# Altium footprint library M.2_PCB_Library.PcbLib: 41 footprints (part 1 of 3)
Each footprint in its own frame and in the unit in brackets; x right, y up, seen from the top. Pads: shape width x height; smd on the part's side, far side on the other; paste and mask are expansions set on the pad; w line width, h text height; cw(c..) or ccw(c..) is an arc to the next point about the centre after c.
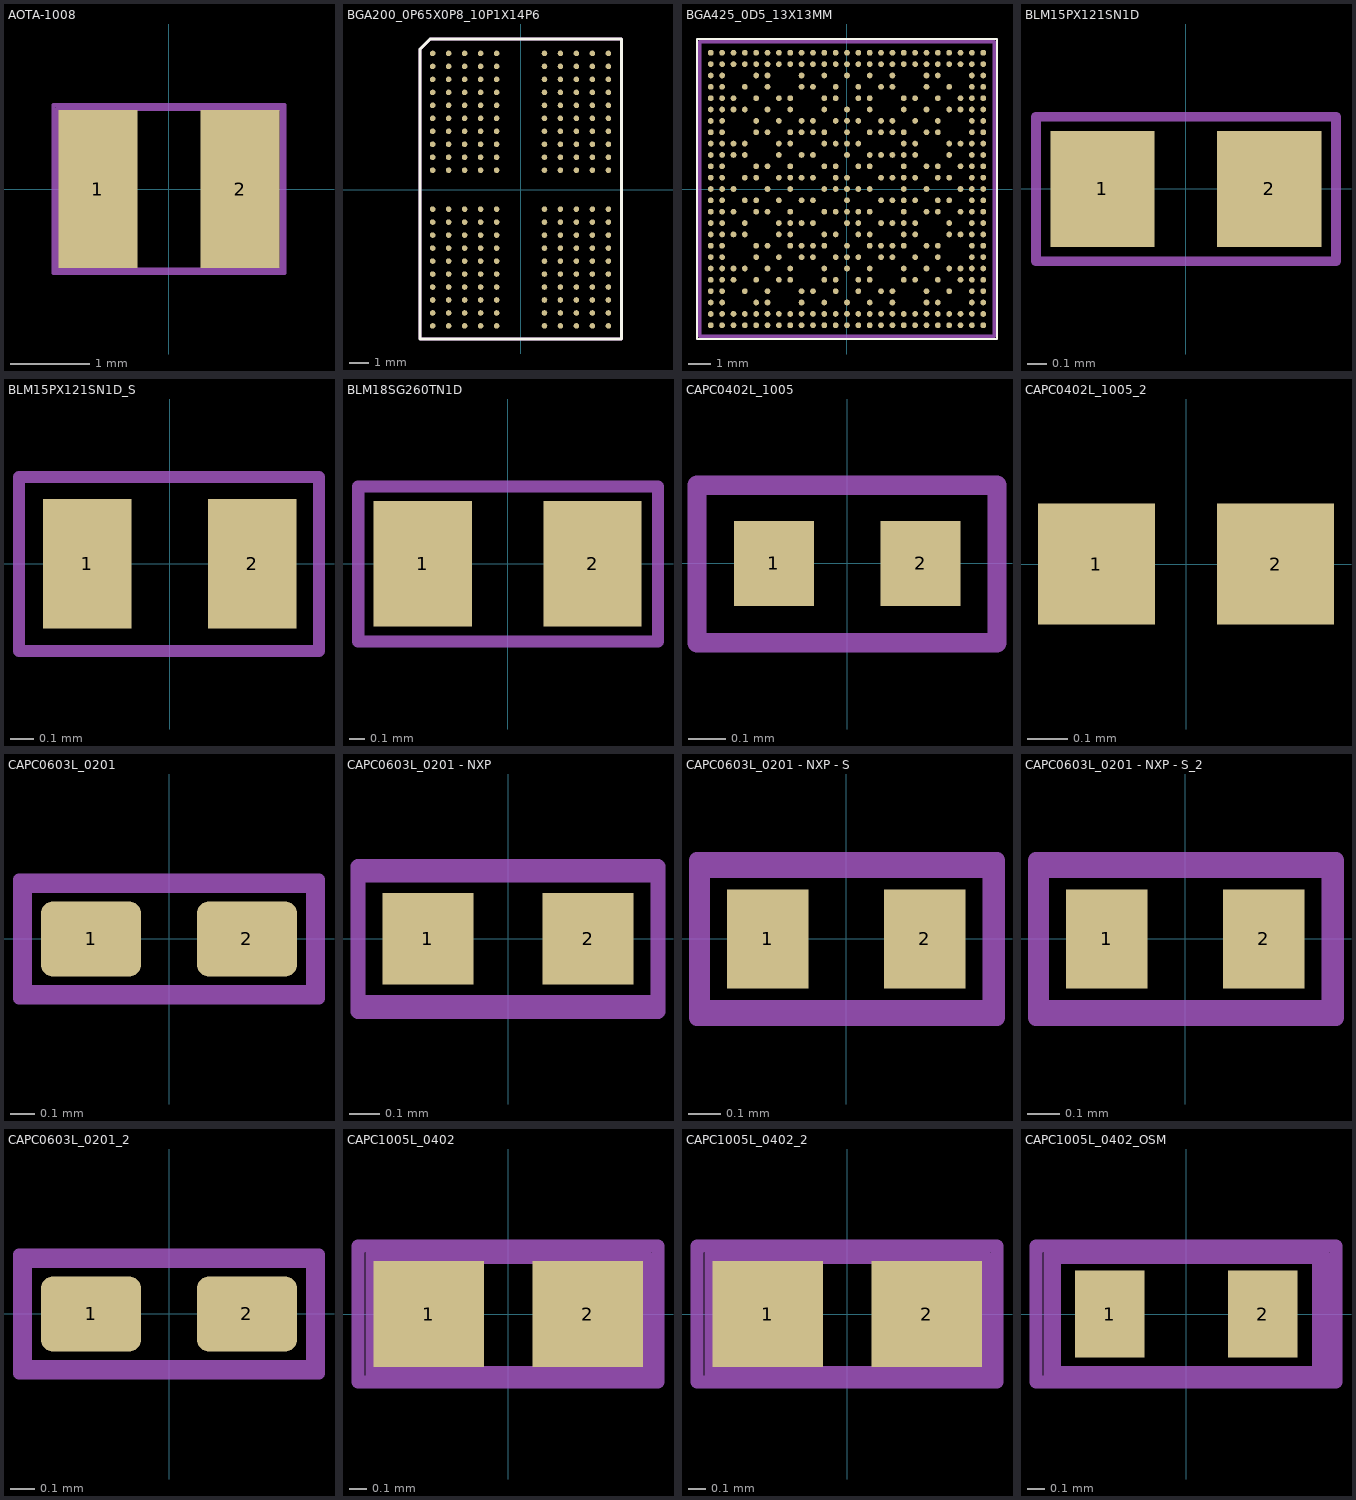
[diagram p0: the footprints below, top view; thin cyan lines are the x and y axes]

## AOTA-1008 [mm]
pads (2):
  rect 1x2 smd paste-0.043 mask+0.038: 1(-0.9,0) 2(0.9,0)
Mechanical 1:
Mechanical 9:
  lines w0.051: -1.46,-1.064 -1.46,1.065 1.465,1.065 1.465,-1.064 -1.46,-1.064
Top Assembly:
  lines w0.051: -1.419,-1.022 -1.419,1.015 1.428,1.015 1.428,-1.022 -1.419,-1.022
  text "'.Designator'" at -0.413,-0.106 h0.2
3D body "AOTA-B252010SR33MT.stp": height 1, standoff 0, extent -1.25,-1 1.25,1

## BGA200_0P65X0P8_10P1X14P6 [mil] "BGA200_0P65X0P8_10P1X14P6"
pads (200):
  round 11 smd mask+2.76: A1(-173.23,268.7) A2(-141.73,268.7) A3(-110.24,268.7) A4(-78.74,268.7) A5(-47.24,268.7) A8(47.24,268.7) A9(78.74,268.7) A10(110.24,268.7) A11(141.73,268.7) A12(173.23,268.7) AA1(-173.23,-243.11) AA2(-141.73,-243.11) AA3(-110.24,-243.11) AA4(-78.74,-243.11) AA5(-47.24,-243.11) AA8(47.24,-243.11) AA9(78.74,-243.11) AA10(110.24,-243.11) AA11(141.73,-243.11) AA12(173.23,-243.11) AB1(-173.23,-268.7) AB2(-141.73,-268.7) AB3(-110.24,-268.7) AB4(-78.74,-268.7) AB5(-47.24,-268.7) AB8(47.24,-268.7) AB9(78.74,-268.7) AB10(110.24,-268.7) AB11(141.73,-268.7) AB12(173.23,-268.7) B1(-173.23,243.11) B2(-141.73,243.11) B3(-110.24,243.11) B4(-78.74,243.11) B5(-47.24,243.11) B8(47.24,243.11) B9(78.74,243.11) B10(110.24,243.11) B11(141.73,243.11) B12(173.23,243.11) C1(-173.23,217.52) C2(-141.73,217.52) C3(-110.24,217.52) C4(-78.74,217.52) C5(-47.24,217.52) C8(47.24,217.52) C9(78.74,217.52) C10(110.24,217.52) C11(141.73,217.52) C12(173.23,217.52) D1(-173.23,191.93) D2(-141.73,191.93) D3(-110.24,191.93) D4(-78.74,191.93) D5(-47.24,191.93) D8(47.24,191.93) D9(78.74,191.93) D10(110.24,191.93) D11(141.73,191.93) D12(173.23,191.93) E1(-173.23,166.34) E2(-141.73,166.34) E3(-110.24,166.34) E4(-78.74,166.34) E5(-47.24,166.34) E8(47.24,166.34) E9(78.74,166.34) E10(110.24,166.34) E11(141.73,166.34) E12(173.23,166.34) F1(-173.23,140.75) F2(-141.73,140.75) F3(-110.24,140.75) F4(-78.74,140.75) F5(-47.24,140.75) F8(47.24,140.75) F9(78.74,140.75) F10(110.24,140.75) F11(141.73,140.75) F12(173.23,140.75) G1(-173.23,115.16) G2(-141.73,115.16) G3(-110.24,115.16) G4(-78.74,115.16) G5(-47.24,115.16) G8(47.24,115.16) G9(78.74,115.16) G10(110.24,115.16) G11(141.73,115.16) G12(173.23,115.16) H1(-173.23,89.57) H2(-141.73,89.57) H3(-110.24,89.57) H4(-78.74,89.57) H5(-47.24,89.57) H8(47.24,89.57) H9(78.74,89.57) H10(110.24,89.57) H11(141.73,89.57) H12(173.23,89.57) J1(-173.23,63.98) J2(-141.73,63.98) J3(-110.24,63.98) J4(-78.74,63.98) J5(-47.24,63.98) J8(47.24,63.98) J9(78.74,63.98) J10(110.24,63.98) J11(141.73,63.98) J12(173.23,63.98) K1(-173.23,38.39) K2(-141.73,38.39) K3(-110.24,38.39) K4(-78.74,38.39) K5(-47.24,38.39) K8(47.24,38.39) K9(78.74,38.39) K10(110.24,38.39) K11(141.73,38.39) K12(173.23,38.39) N1(-173.23,-38.39) N2(-141.73,-38.39) N3(-110.24,-38.39) N4(-78.74,-38.39) N5(-47.24,-38.39) N8(47.24,-38.39) N9(78.74,-38.39) N10(110.24,-38.39) N11(141.73,-38.39) N12(173.23,-38.39) P1(-173.23,-63.98) P2(-141.73,-63.98) P3(-110.24,-63.98) P4(-78.74,-63.98) P5(-47.24,-63.98) P8(47.24,-63.98) P9(78.74,-63.98) P10(110.24,-63.98) P11(141.73,-63.98) P12(173.23,-63.98) R1(-173.23,-89.57) R2(-141.73,-89.57) R3(-110.24,-89.57) R4(-78.74,-89.57) R5(-47.24,-89.57) R8(47.24,-89.57) R9(78.74,-89.57) R10(110.24,-89.57) R11(141.73,-89.57) R12(173.23,-89.57) T1(-173.23,-115.16) T2(-141.73,-115.16) T3(-110.24,-115.16) T4(-78.74,-115.16) T5(-47.24,-115.16) T8(47.24,-115.16) T9(78.74,-115.16) T10(110.24,-115.16) T11(141.73,-115.16) T12(173.23,-115.16) U1(-173.23,-140.75) U2(-141.73,-140.75) U3(-110.24,-140.75) U4(-78.74,-140.75) U5(-47.24,-140.75) U8(47.24,-140.75) U9(78.74,-140.75) U10(110.24,-140.75) U11(141.73,-140.75) U12(173.23,-140.75) V1(-173.23,-166.34) V2(-141.73,-166.34) V3(-110.24,-166.34) V4(-78.74,-166.34) V5(-47.24,-166.34) V8(47.24,-166.34) V9(78.74,-166.34) V10(110.24,-166.34) V11(141.73,-166.34) V12(173.23,-166.34) W1(-173.23,-191.93) W2(-141.73,-191.93) W3(-110.24,-191.93) W4(-78.74,-191.93) W5(-47.24,-191.93) W8(47.24,-191.93) W9(78.74,-191.93) W10(110.24,-191.93) W11(141.73,-191.93) W12(173.23,-191.93) Y1(-173.23,-217.52) Y2(-141.73,-217.52) Y3(-110.24,-217.52) Y4(-78.74,-217.52) Y5(-47.24,-217.52) Y8(47.24,-217.52) Y9(78.74,-217.52) Y10(110.24,-217.52) Y11(141.73,-217.52) Y12(173.23,-217.52)
Top Overlay:
  lines w6: -198.21,-294.41 198.86,-294.41 198.86,297.15 -178.07,297.15 -198.21,277.01 -198.21,-294.41
Mechanical 7:
  text "'.Designator'" at -66.73,-11.32 h50
  text "AB" at -238.87,-258 h25
  text "A" at -238.87,277 h25
  text "1" at -194.7,322 h25
  text "12" at 215.16,299.31 h25
Top Assembly:
  lines w6: -198.31,-294.43 -198.31,276.91 -178.07,297.15 198.82,297.15 198.82,-294.43 -198.31,-294.43
Mechanical 18:
  text "K8" at 47.24,38.71 h0.4
  text "N8" at 47.24,-38.07 h0.4
  text "K5" at -47.24,38.71 h0.4
  text "N5" at -47.24,-38.07 h0.4
  text "AB12" at 173.23,-268.06 h0.4
  text "A11" at 141.73,269.18 h0.4
  text "A2" at -141.73,269.02 h0.4
  text "A1" at -173.23,269.02 h0.4
  text "AB11" at 141.73,-268.06 h0.4
  text "AB2" at -141.73,-268.22 h0.4
  text "AB1" at -173.23,-268.22 h0.4
  text "AA12" at 173.23,-242.47 h0.4
  text "AA1" at -173.23,-242.63 h0.4
  text "B12" at 173.23,243.59 h0.4
  text "B1" at -173.23,243.43 h0.4
  text "A12" at 173.23,269.18 h0.4
  text "G11" at 141.73,115.64 h0.4
  text "T1" at -173.23,-114.84 h0.4
  text "V1" at -173.23,-166.02 h0.4
  text "D2" at -141.73,192.25 h0.4
  text "T3" at -110.24,-114.84 h0.4
  text "V12" at 173.23,-165.86 h0.4
  text "T12" at 173.23,-114.68 h0.4
  text "Y12" at 173.23,-217.04 h0.4
  text "P12" at 173.23,-63.5 h0.4
  text "N11" at 141.73,-37.91 h0.4
  text "J12" at 173.23,64.46 h0.4
  text "K11" at 141.73,38.87 h0.4
  text "G12" at 173.23,115.64 h0.4
  text "E12" at 173.23,166.82 h0.4
  text "AB8" at 47.24,-268.22 h0.4
  text "AB10" at 110.24,-268.06 h0.4
  text "Y8" at 47.24,-217.2 h0.4
  text "W9" at 78.74,-191.61 h0.4
  text "V8" at 47.24,-166.02 h0.4
  text "W11" at 141.73,-191.45 h0.4
  text "T10" at 110.24,-114.68 h0.4
  text "N9" at 78.74,-38.07 h0.4
  text "P10" at 110.24,-63.5 h0.4
  text "K9" at 78.74,38.71 h0.4
  text "J10" at 110.24,64.46 h0.4
  text "G8" at 47.24,115.48 h0.4
  text "C8" at 47.24,217.84 h0.4
  text "E8" at 47.24,166.66 h0.4
  text "G10" at 110.24,115.64 h0.4
  text "D9" at 78.74,192.25 h0.4
  text "A10" at 110.24,269.18 h0.4
  text "AB5" at -47.24,-268.22 h0.4
  text "W4" at -78.74,-191.61 h0.4
  text "Y5" at -47.24,-217.2 h0.4
  text "N4" at -78.74,-38.07 h0.4
  text "P3" at -110.24,-63.66 h0.4
  text "K4" at -78.74,38.71 h0.4
  text "J3" at -110.24,64.3 h0.4
  text "G3" at -110.24,115.48 h0.4
  text "G5" at -47.24,115.48 h0.4
  text "Y1" at -173.23,-217.2 h0.4
  text "D4" at -78.74,192.25 h0.4
  text "W2" at -141.73,-191.61 h0.4
  text "AB3" at -110.24,-268.22 h0.4
  text "N2" at -141.73,-38.07 h0.4
  text "P1" at -173.23,-63.66 h0.4
  text "G1" at -173.23,115.48 h0.4
  text "J1" at -173.23,64.3 h0.4
  text "K2" at -141.73,38.71 h0.4
  text "C5" at -47.24,217.84 h0.4
  text "C1" at -173.23,217.84 h0.4
  text "D11" at 141.73,192.41 h0.4
  text "C12" at 173.23,218 h0.4
  text "E1" at -173.23,166.66 h0.4
  text "A3" at -110.24,269.02 h0.4
  text "E5" at -47.24,166.66 h0.4
  text "V5" at -47.24,-166.02 h0.4
  text "T8" at 47.24,-114.84 h0.4
  text "T5" at -47.24,-114.84 h0.4
  text "J11" at 141.73,64.46 h0.4
  text "R2" at -141.73,-89.25 h0.4
  text "P9" at 78.74,-63.66 h0.4
  text "R4" at -78.74,-89.25 h0.4
  text "C4" at -78.74,217.84 h0.4
  text "F11" at 141.73,141.23 h0.4
  text "B4" at -78.74,243.43 h0.4
  text "C3" at -110.24,217.84 h0.4
  text "P2" at -141.73,-63.66 h0.4
  text "F2" at -141.73,141.07 h0.4
  text "T11" at 141.73,-114.68 h0.4
  text "Y9" at 78.74,-217.2 h0.4
  text "P11" at 141.73,-63.5 h0.4
  text "AA2" at -141.73,-242.63 h0.4
  text "T2" at -141.73,-114.84 h0.4
  text "AA11" at 141.73,-242.47 h0.4
  text "U9" at 78.74,-140.43 h0.4
  text "D3" at -110.24,192.25 h0.4
  text "F4" at -78.74,141.07 h0.4
  text "Y2" at -141.73,-217.2 h0.4
  text "Y11" at 141.73,-217.04 h0.4
  text "A5" at -47.24,269.02 h0.4
  text "H2" at -141.73,89.89 h0.4
  text "AA9" at 78.74,-242.63 h0.4
  text "E9" at 78.74,166.66 h0.4
  text "J4" at -78.74,64.3 h0.4
  text "H9" at 78.74,89.89 h0.4
  text "E11" at 141.73,166.82 h0.4
  text "V10" at 110.24,-165.86 h0.4
  text "U4" at -78.74,-140.43 h0.4
  text "C2" at -141.73,217.84 h0.4
  text "V11" at 141.73,-165.86 h0.4
  text "E3" at -110.24,166.66 h0.4
  text "AA4" at -78.74,-242.63 h0.4
  text "J9" at 78.74,64.3 h0.4
  text "J5" at -47.24,64.3 h0.4
  text "V4" at -78.74,-166.02 h0.4
  text "E4" at -78.74,166.66 h0.4
  text "B2" at -141.73,243.43 h0.4
  text "C9" at 78.74,217.84 h0.4
  text "U2" at -141.73,-140.43 h0.4
  text "H3" at -110.24,89.89 h0.4
  text "R3" at -110.24,-89.25 h0.4
  text "V2" at -141.73,-166.02 h0.4
  text "Y4" at -78.74,-217.2 h0.4
  text "E2" at -141.73,166.66 h0.4
  text "V3" at -110.24,-166.02 h0.4
  text "Y10" at 110.24,-217.04 h0.4
  text "J2" at -141.73,64.3 h0.4
  text "P4" at -78.74,-63.66 h0.4
  text "B3" at -110.24,243.43 h0.4
  text "U3" at -110.24,-140.43 h0.4
  text "W5" at -47.24,-191.61 h0.4
  text "U5" at -47.24,-140.43 h0.4
  text "H5" at -47.24,89.89 h0.4
  text "AA10" at 110.24,-242.47 h0.4
  text "W12" at 173.23,-191.45 h0.4
  text "U10" at 110.24,-140.27 h0.4
  text "R12" at 173.23,-89.09 h0.4
  text "N12" at 173.23,-37.91 h0.4
  text "N10" at 110.24,-37.91 h0.4
  text "K12" at 173.23,38.87 h0.4
  text "K10" at 110.24,38.87 h0.4
  text "H12" at 173.23,90.05 h0.4
  text "D12" at 173.23,192.41 h0.4
  text "F10" at 110.24,141.23 h0.4
  text "B10" at 110.24,243.59 h0.4
  text "AB9" at 78.74,-268.22 h0.4
  text "AA8" at 47.24,-242.63 h0.4
  text "W8" at 47.24,-191.61 h0.4
  text "U8" at 47.24,-140.43 h0.4
  text "R8" at 47.24,-89.25 h0.4
  text "H8" at 47.24,89.89 h0.4
  text "F8" at 47.24,141.07 h0.4
  text "F5" at -47.24,141.07 h0.4
  text "D8" at 47.24,192.25 h0.4
  text "A9" at 78.74,269.02 h0.4
  text "B8" at 47.24,243.43 h0.4
  text "AB4" at -78.74,-268.22 h0.4
  text "AA5" at -47.24,-242.63 h0.4
  text "D5" at -47.24,192.25 h0.4
  text "A4" at -78.74,269.02 h0.4
  text "B5" at -47.24,243.43 h0.4
  text "W1" at -173.23,-191.61 h0.4
  text "N3" at -110.24,-38.07 h0.4
  text "R1" at -173.23,-89.25 h0.4
  text "N1" at -173.23,-38.07 h0.4
  text "K3" at -110.24,38.71 h0.4
  text "K1" at -173.23,38.71 h0.4
  text "F3" at -110.24,141.07 h0.4
  text "H1" at -173.23,89.89 h0.4
  text "D1" at -173.23,192.25 h0.4
  text "AA3" at -110.24,-242.63 h0.4
  text "R5" at -47.24,-89.25 h0.4
  text "W10" at 110.24,-191.45 h0.4
  text "B11" at 141.73,243.59 h0.4
  text "A8" at 47.24,269.02 h0.4
  text "U12" at 173.23,-140.27 h0.4
  text "T4" at -78.74,-114.84 h0.4
  text "U1" at -173.23,-140.43 h0.4
  text "F1" at -173.23,141.07 h0.4
  text "G4" at -78.74,115.48 h0.4
  text "F12" at 173.23,141.23 h0.4
  text "G9" at 78.74,115.48 h0.4
  text "T9" at 78.74,-114.84 h0.4
  text "C10" at 110.24,218 h0.4
  text "F9" at 78.74,141.07 h0.4
  text "B9" at 78.74,243.43 h0.4
  text "H11" at 141.73,90.05 h0.4
  text "E10" at 110.24,166.82 h0.4
  text "H10" at 110.24,90.05 h0.4
  text "R9" at 78.74,-89.25 h0.4
  text "D10" at 110.24,192.41 h0.4
  text "V9" at 78.74,-166.02 h0.4
  text "P5" at -47.24,-63.66 h0.4
  text "C11" at 141.73,218 h0.4
  text "Y3" at -110.24,-217.2 h0.4
  text "H4" at -78.74,89.89 h0.4
  text "U11" at 141.73,-140.27 h0.4
  text "G2" at -141.73,115.48 h0.4
  text "P8" at 47.24,-63.66 h0.4
  text "W3" at -110.24,-191.61 h0.4
  text "R11" at 141.73,-89.09 h0.4
  text "R10" at 110.24,-89.09 h0.4
  text "J8" at 47.24,64.3 h0.4
Mechanical 19:
  text "AB" at -231,-257 h25
  text "A" at -236.22,259.84 h25
  text "12" at 173.23,307.09 h25
  text "1" at -173.23,307.09 h25
3D body: height 35.43, standoff 0, extent -198.82,-295.28 198.82,295.28

## BGA425_0D5_13X13MM [mil] "BGA425_0D5_13X13MM"
pads (425):
  round 10 smd: A1(-236.22,236.22) A2(-216.54,236.22) A3(-196.85,236.22) A4(-177.16,236.22) A5(-157.48,236.22) A6(-137.8,236.22) A7(-118.11,236.22) A8(-98.42,236.22) A9(-78.74,236.22) A10(-59.06,236.22) A11(-39.37,236.22) A12(-19.68,236.22) A13(0,236.22) A14(19.68,236.22) A15(39.37,236.22) A16(59.06,236.22) A17(78.74,236.22) A18(98.42,236.22) A19(118.11,236.22) A20(137.8,236.22) A21(157.48,236.22) A22(177.16,236.22) A23(196.85,236.22) A24(216.54,236.22) A25(236.22,236.22) AA1(-236.22,-157.48) AA2(-216.54,-157.48) AA3(-196.85,-157.48) AA5(-157.48,-157.48) AA7(-118.11,-157.48) AA8(-98.42,-157.48) AA11(-39.37,-157.48) AA12(-19.68,-157.48) AA14(19.68,-157.48) AA15(39.37,-157.48) AA18(98.42,-157.48) AA19(118.11,-157.48) AA21(157.48,-157.48) AA23(196.85,-157.48) AA24(216.54,-157.48) AA25(236.22,-157.48) AB1(-236.22,-177.16) AB2(-216.54,-177.16) AB4(-177.16,-177.16) AB6(-137.8,-177.16) AB9(-78.74,-177.16) AB10(-59.06,-177.16) AB12(-19.68,-177.16) AB14(19.68,-177.16) AB16(59.06,-177.16) AB17(78.74,-177.16) AB20(137.8,-177.16) AB22(177.16,-177.16) AB24(216.54,-177.16) AB25(236.22,-177.16) AC1(-236.22,-196.85) AC2(-216.54,-196.85) AC5(-157.48,-196.85) AC6(-137.8,-196.85) AC9(-78.74,-196.85) AC11(-39.37,-196.85) AC13(0,-196.85) AC15(39.37,-196.85) AC17(78.74,-196.85) AC20(137.8,-196.85) AC21(157.48,-196.85) AC24(216.54,-196.85) AC25(236.22,-196.85) AD1(-236.22,-216.54) AD2(-216.54,-216.54) AD3(-196.85,-216.54) AD4(-177.16,-216.54) AD5(-157.48,-216.54) AD6(-137.8,-216.54) AD7(-118.11,-216.54) AD8(-98.42,-216.54) AD9(-78.74,-216.54) AD10(-59.06,-216.54) AD11(-39.37,-216.54) AD12(-19.68,-216.54) AD13(0,-216.54) AD14(19.68,-216.54) AD15(39.37,-216.54) AD16(59.06,-216.54) AD17(78.74,-216.54) AD18(98.42,-216.54) AD19(118.11,-216.54) AD20(137.8,-216.54) AD21(157.48,-216.54) AD22(177.16,-216.54) AD23(196.85,-216.54) AD24(216.54,-216.54) AD25(236.22,-216.54) AE1(-236.22,-236.22) AE2(-216.54,-236.22) AE3(-196.85,-236.22) AE4(-177.16,-236.22) AE5(-157.48,-236.22) AE6(-137.8,-236.22) AE7(-118.11,-236.22) AE8(-98.42,-236.22) AE9(-78.74,-236.22) AE10(-59.06,-236.22) AE11(-39.37,-236.22) AE12(-19.68,-236.22) AE13(0,-236.22) AE14(19.68,-236.22) AE15(39.37,-236.22) AE16(59.06,-236.22) AE17(78.74,-236.22) AE18(98.42,-236.22) AE19(118.11,-236.22) AE20(137.8,-236.22) AE21(157.48,-236.22) AE22(177.16,-236.22) AE23(196.85,-236.22) AE24(216.54,-236.22) AE25(236.22,-236.22) B1(-236.22,216.54) B2(-216.54,216.54) B3(-196.85,216.54) B4(-177.16,216.54) B5(-157.48,216.54) B6(-137.8,216.54) B7(-118.11,216.54) B8(-98.42,216.54) B9(-78.74,216.54) B10(-59.06,216.54) B11(-39.37,216.54) B12(-19.68,216.54) B13(0,216.54) B14(19.68,216.54) B15(39.37,216.54) B16(59.06,216.54) B17(78.74,216.54) B18(98.42,216.54) B19(118.11,216.54) B20(137.8,216.54) B21(157.48,216.54) B22(177.16,216.54) B23(196.85,216.54) B24(216.54,216.54) B25(236.22,216.54) C1(-236.22,196.85) C2(-216.54,196.85) C5(-157.48,196.85) C6(-137.8,196.85) C9(-78.74,196.85) C11(-39.37,196.85) C13(0,196.85) C15(39.37,196.85) C17(78.74,196.85) C20(137.8,196.85) C21(157.48,196.85) C24(216.54,196.85) C25(236.22,196.85) D1(-236.22,177.16) D2(-216.54,177.16) D4(-177.16,177.16) D6(-137.8,177.16) D9(-78.74,177.16) D10(-59.06,177.16) D12(-19.68,177.16) D14(19.68,177.16) D16(59.06,177.16) D17(78.74,177.16) D20(137.8,177.16) D22(177.16,177.16) D24(216.54,177.16) D25(236.22,177.16) E1(-236.22,157.48) E2(-216.54,157.48) E3(-196.85,157.48) E5(-157.48,157.48) E7(-118.11,157.48) E8(-98.42,157.48) E11(-39.37,157.48) E12(-19.68,157.48) E14(19.68,157.48) E15(39.37,157.48) E18(98.42,157.48) E19(118.11,157.48) E21(157.48,157.48) E23(196.85,157.48) E24(216.54,157.48) E25(236.22,157.48) F1(-236.22,137.8) F2(-216.54,137.8) F3(-196.85,137.8) F4(-177.16,137.8) F6(-137.8,137.8) F8(-98.42,137.8) F11(-39.37,137.8) F13(0,137.8) F15(39.37,137.8) F18(98.42,137.8) F20(137.8,137.8) F22(177.16,137.8) F23(196.85,137.8) F24(216.54,137.8) F25(236.22,137.8) G1(-236.22,118.11) G2(-216.54,118.11) G5(-157.48,118.11) G7(-118.11,118.11) G9(-78.74,118.11) G10(-59.06,118.11) G12(-19.68,118.11) G13(0,118.11) G14(19.68,118.11) G16(59.06,118.11) G17(78.74,118.11) G19(118.11,118.11) G21(157.48,118.11) G24(216.54,118.11) G25(236.22,118.11) H1(-236.22,98.42) H2(-216.54,98.42) H5(-157.48,98.42) H6(-137.8,98.42) H8(-98.42,98.42) H9(-78.74,98.42) H10(-59.06,98.42) H11(-39.37,98.42) H13(0,98.42) H15(39.37,98.42) H16(59.06,98.42) H17(78.74,98.42) H18(98.42,98.42) H20(137.8,98.42) H21(157.48,98.42) H24(216.54,98.42) H25(236.22,98.42) J1(-236.22,78.74) J2(-216.54,78.74) J3(-196.85,78.74) J4(-177.16,78.74) J7(-118.11,78.74) J8(-98.42,78.74) J11(-39.37,78.74) J12(-19.68,78.74) J13(0,78.74) J14(19.68,78.74) J18(98.42,78.74) J19(118.11,78.74) J22(177.16,78.74) J23(196.85,78.74) J24(216.54,78.74) J25(236.22,78.74) K1(-236.22,59.06) K2(-216.54,59.06) K3(-196.85,59.06) K4(-177.16,59.06) K7(-118.11,59.06) K9(-78.74,59.06) K10(-59.06,59.06) K13(0,59.06) K15(39.37,59.06) K16(59.06,59.06) K17(78.74,59.06) K18(98.42,59.06) K19(118.11,59.06) K22(177.16,59.06) K24(216.54,59.06) K25(236.22,59.06) L1(-236.22,39.37) L2(-216.54,39.37) L5(-157.48,39.37) L6(-137.8,39.37) L8(-98.42,39.37) L11(-39.37,39.37) L12(-19.68,39.37) L14(19.68,39.37) L15(39.37,39.37) L18(98.42,39.37) L20(137.8,39.37) L21(157.48,39.37) L23(196.85,39.37) L24(216.54,39.37) L25(236.22,39.37) M1(-236.22,19.68) M2(-216.54,19.68) M4(-177.16,19.68) M5(-157.48,19.68) M7(-118.11,19.68) M8(-98.42,19.68) M9(-78.74,19.68) M10(-59.06,19.68) M12(-19.68,19.68) M13(0,19.68) M16(59.06,19.68) M17(78.74,19.68) M18(98.42,19.68) M19(118.11,19.68) M21(157.48,19.68) M22(177.16,19.68) M24(216.54,19.68) M25(236.22,19.68) N1(-236.22,0) N2(-216.54,0) N3(-196.85,0) N6(-137.8,0) N8(-98.42,0) N11(-39.37,0) N12(-19.68,0) N13(0,0) N14(19.68,0) N15(39.37,0) N18(98.42,0) N20(137.8,0) N23(196.85,0) N24(216.54,0) N25(236.22,0) P1(-236.22,-19.68) P2(-216.54,-19.68) P4(-177.16,-19.68) P5(-157.48,-19.68) P7(-118.11,-19.68) P9(-78.74,-19.68) P10(-59.06,-19.68) P13(0,-19.68) P16(59.06,-19.68) P17(78.74,-19.68) P18(98.42,-19.68) P19(118.11,-19.68) P21(157.48,-19.68) P22(177.16,-19.68) P24(216.54,-19.68) P25(236.22,-19.68) R1(-236.22,-39.37) R2(-216.54,-39.37) R3(-196.85,-39.37) R5(-157.48,-39.37) R6(-137.8,-39.37) R8(-98.42,-39.37) R11(-39.37,-39.37) R12(-19.68,-39.37) R13(0,-39.37) R14(19.68,-39.37) R15(39.37,-39.37) R18(98.42,-39.37) R20(137.8,-39.37) R21(157.48,-39.37) R23(196.85,-39.37) R24(216.54,-39.37) R25(236.22,-39.37) T1(-236.22,-59.06) T2(-216.54,-59.06) T4(-177.16,-59.06) T7(-118.11,-59.06) T8(-98.42,-59.06) T9(-78.74,-59.06) T10(-59.06,-59.06) T13(0,-59.06) T14(19.68,-59.06) T16(59.06,-59.06) T17(78.74,-59.06) T18(98.42,-59.06) T19(118.11,-59.06) T22(177.16,-59.06) T24(216.54,-59.06) T25(236.22,-59.06) U1(-236.22,-78.74) U2(-216.54,-78.74) U3(-196.85,-78.74) U4(-177.16,-78.74) U7(-118.11,-78.74) U8(-98.42,-78.74) U11(-39.37,-78.74) U12(-19.68,-78.74) U14(19.68,-78.74) U15(39.37,-78.74) U18(98.42,-78.74) U19(118.11,-78.74) U22(177.16,-78.74) U23(196.85,-78.74) U24(216.54,-78.74) U25(236.22,-78.74) V1(-236.22,-98.42) V2(-216.54,-98.42) V5(-157.48,-98.42) V6(-137.8,-98.42) V8(-98.42,-98.42) V9(-78.74,-98.42) V10(-59.06,-98.42) V11(-39.37,-98.42) V13(0,-98.42) V15(39.37,-98.42) V16(59.06,-98.42) V17(78.74,-98.42) V18(98.42,-98.42) V20(137.8,-98.42) V21(157.48,-98.42) V24(216.54,-98.42) V25(236.22,-98.42) W1(-236.22,-118.11) W2(-216.54,-118.11) W5(-157.48,-118.11) W7(-118.11,-118.11) W9(-78.74,-118.11) W10(-59.06,-118.11) W12(-19.68,-118.11) W13(0,-118.11) W14(19.68,-118.11) W16(59.06,-118.11) W17(78.74,-118.11) W19(118.11,-118.11) W21(157.48,-118.11) W24(216.54,-118.11) W25(236.22,-118.11) Y1(-236.22,-137.8) Y2(-216.54,-137.8) Y3(-196.85,-137.8) Y4(-177.16,-137.8) Y6(-137.8,-137.8) Y8(-98.42,-137.8) Y11(-39.37,-137.8) Y13(0,-137.8) Y15(39.37,-137.8) Y18(98.42,-137.8) Y20(137.8,-137.8) Y22(177.16,-137.8) Y23(196.85,-137.8) Y24(216.54,-137.8) Y25(236.22,-137.8)
Top Overlay:
  lines w4: -260.09,-260 -260.09,260.04 260.1,260.04 260.1,-260 -260.09,-260
Top Assembly:
  lines w6: -255,-255 255,-255 255,255 -255,255 -255,-255
3D body: height 35.04, standoff 0, extent -257.87,-257.87 257.87,257.87

## BLM15PX121SN1D [mm]
pads (2):
  rect 0.54x0.6 smd: 1(-0.432,0) 2(0.432,0)
Top Courtyard:
  lines w0.051: -0.777,-0.375 -0.777,0.374 0.778,0.374 0.778,-0.375 -0.777,-0.375
3D body "step_temp.STEP": height 0.55, standoff 0, extent -0.5,-0.25 0.5,0.25

## BLM15PX121SN1D_S [mil]
pads (2):
  rect 15x22 smd: 1(-14.01,0) 2(14.01,0)
Top Courtyard:
  lines w2: -25.57,-14.76 25.34,-14.76 25.34,14.73 -25.57,14.73 -25.57,-14.76
3D body "step_temp.STEP": height 21.65, standoff 0, extent -19.68,-9.84 19.68,9.84

## BLM18SG260TN1D [mil]
height 55.12
pads (2):
  rect 25x32 smd mask+2.5: 1(-21.62,0) 2(21.62,0)
Mechanical 1:
Mechanical 9:
  lines w3: -38.13,-19.81 -38.13,19.73 38.28,19.73 38.28,-19.81 -38.13,-19.81
Top Assembly:
  lines w3: -38.03,-19.81 -38.03,19.69 38.21,19.69 38.21,-19.81 -38.03,-19.81
  text "'.Designator'" at -45.59,-6.08 h20
3D body "BLM18SG260TN1D.step": height 25.59, standoff 0, extent -31.5,-15.75 31.5,15.75

## CAPC0402L_1005 [mm]
pads (2):
  rect 0.212x0.225 smd: 1(-0.194,0) 2(0.194,0)
Top Courtyard:
  lines w0.051: -0.398,-0.21 0.396,-0.21 0.396,0.207 -0.398,0.207 -0.398,-0.21
3D body "CAP_CL02_SAM.step": height 0.22, standoff 0, extent -0.2,-0.1 0.2,0.1

## CAPC0402L_1005_2 [mm]
pads (2):
  rect 0.29x0.3 smd: 1(-0.222,0) 2(0.222,0)
3D body "CAP_CL02_SAM.step": height 0.22, standoff 0, extent -0.2,-0.1 0.2,0.1

## CAPC0603L_0201 [mil]
pads (2):
  rrect30% 16x12 smd mask+1: 1(-12.5,0) 2(12.5,0)
Mechanical 1:
Mechanical 9:
  lines w1.97: -24.04,-9.54 -24.04,9.52 24.04,9.52 24.04,-9.54 -24.04,-9.54
  text "'.Designator'" at 1.03,-3.44 h4
  text "'.Comment'" at 11.3,2.15 h4
Top Assembly:
  lines w1.97: -22.93,-8.37 -22.93,8.37 22.93,8.37 22.93,-8.37 -22.93,-8.37
  text "'.Designator'" at -21.75,-3.94 h13
3D body "CAP0201 (0603).step": height 11.81, standoff 0, extent -11.81,-6.1 11.81,5.71

## CAPC0603L_0201 - NXP [mil]
pads (2):
  rect 12x12 smd: 1(-10.5,0) 2(10.5,0)
Mechanical 1:
Mechanical 9:
  lines w1.97: -19.68,-9.54 19.68,-9.54 19.68,9.52 -19.68,9.52 -19.68,-9.54
Top Assembly:
  lines w1.97: -19.68,-8.37 19.68,-8.37 19.68,8.37 -19.68,8.37 -19.68,-8.37
  text "'.Designator'" at -21.75,-3.94 h13
3D body "CAP0201 (0603).step": height 11.81, standoff 0, extent -11.81,-6.1 11.81,5.71

## CAPC0603L_0201 - NXP - S [mil]
pads (2):
  rect 9.84x12 smd: 1(-9.5,0) 2(9.5,0)
Mechanical 1:
Mechanical 9:
  lines w1.97: -18.08,-9.54 -18.08,9.52 18.24,9.52 18.24,-9.54 -18.08,-9.54
Top Assembly:
  lines w1.97: -17.48,-8.37 -17.48,8.37 17.47,8.37 17.47,-8.37 -17.48,-8.37
  text "'.Designator'" at -26.02,-3.79 h13
3D body "CAP0201 (0603).step": height 11.81, standoff 0, extent -11.81,-6.1 11.81,5.71

## CAPC0603L_0201 - NXP - S_2 [mil]
pads (2):
  rect 9.84x12 smd: 1(-9.5,0) 2(9.5,0)
Mechanical 1:
Mechanical 9:
  lines w1.97: -18.08,-9.54 -18.08,9.52 18.24,9.52 18.24,-9.54 -18.08,-9.54
Top Assembly:
  lines w1.97: -17.48,-8.37 -17.48,8.37 17.47,8.37 17.47,-8.37 -17.48,-8.37
  text "'.Designator'" at -26.02,-3.79 h13
3D body "CAP0201 (0603).step": height 11.81, standoff 0, extent -11.81,-6.1 11.81,5.71

## CAPC0603L_0201_2 [mil]
pads (2):
  rrect30% 16x12 smd mask+1: 1(-12.5,0) 2(12.5,0)
Mechanical 1:
Mechanical 9:
  lines w1.97: -24.04,-9.54 24.04,-9.54 24.04,9.52 -24.04,9.52 -24.04,-9.54
  text "'.Comment'" at 11.3,2.15 h4
  text "'.Designator'" at 1.03,-3.44 h4
Top Assembly:
  lines w1.97: -22.93,-8.37 22.93,-8.37 22.93,8.37 -22.93,8.37 -22.93,-8.37
  text "'.Designator'" at -21.75,-3.94 h13
3D body "CAP0201 (0603).step": height 11.81, standoff 0, extent -11.81,-6.1 11.81,5.71

## CAPC1005L_0402 [mil] "EMI recommended"
pads (2):
  rect 25x24 smd mask+1.5: 1(-18,0) 2(18,0)
Mechanical 1:
Mechanical 9:
  lines w3: -33.96,-15.35 33.86,-15.35 33.86,15.35 -33.96,15.35 -33.96,-15.35
  text "'.Comment'" at -0.04,-7.87 h4
  text "'.Designator'" at 3.19,-7.87 h4
Top Assembly:
  lines w4: -30.32,-13.78 30.41,-13.78 30.41,13.29 -30.32,13.29 -30.32,-13.78
  text "'.Designator'" at -27.26,-5.71 h20
3D body "CAP0402.step": height 18.5, standoff -1.18, extent -19.68,-9.68 19.69,10.01

## CAPC1005L_0402_2 [mil]
pads (2):
  rect 25x24 smd mask+1.5: 1(-18,0) 2(18,0)
Mechanical 1:
Mechanical 9:
  lines w3: -33.96,-15.35 33.86,-15.35 33.86,15.35 -33.96,15.35 -33.96,-15.35
  text "'.Comment'" at -0.04,-7.87 h4
  text "'.Designator'" at 3.19,-7.87 h4
Top Assembly:
  lines w4: -30.32,-13.78 30.41,-13.78 30.41,13.29 -30.32,13.29 -30.32,-13.78
  text "'.Designator'" at -27.26,-5.71 h20
3D body "CAP0402.step": height 18.5, standoff -1.18, extent -19.68,-9.68 19.69,10.01

## CAPC1005L_0402_OSM [mm] "EMI recommended"
pads (2):
  rect 0.4x0.5 smd mask+0.038: 1(-0.44,0) 2(0.44,0)
Mechanical 1:
Mechanical 9:
  lines w0.076: -0.863,-0.39 -0.863,0.39 0.86,0.39 0.86,-0.39 -0.863,-0.39
  text "'.Designator'" at 0.081,-0.2 h0.1
  text "'.Comment'" at -0.001,-0.2 h0.1
Top Assembly:
  lines w0.102: -0.77,-0.35 -0.77,0.337 0.773,0.337 0.773,-0.35 -0.77,-0.35
  text "'.Designator'" at -0.693,-0.145 h0.51
3D body "CAP0402.step": height 0.47, standoff -0.03, extent -0.5,-0.246 0.5,0.254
